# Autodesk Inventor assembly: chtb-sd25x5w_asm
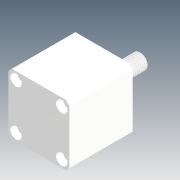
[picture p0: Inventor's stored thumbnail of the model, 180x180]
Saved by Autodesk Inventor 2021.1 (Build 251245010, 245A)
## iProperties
Company: Microsoft
Created: 2018-05
Part Number: chtb-sd25x5w_asm
Description: STEP AP214
Document SubType Name: Assembly
Designer: user
Title: chtb-sd25x5w_asm.STEP
Author: Windows
Revision Number: ÈÎºÎ
Sending System: SolidWorks 2015
Preprocessor: SwSTEP 2.0
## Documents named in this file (4)
- D:\Vault_2016\Projekty\Clamptek\Hydraulic\CHTB\CHTB-25\Inventor\chtb-sd25x5w\chtb-sd25x5w_asm.iam
- D:\Vault_2016\Projekty\Clamptek\Hydraulic\CHTB\CHTB-25\Inventor\chtb-sd25x5w\CHTB-25QG.ipt
- D:\Vault_2016\Projekty\Clamptek\Hydraulic\CHTB\CHTB-25\Inventor\chtb-sd25x5w\CHTB-SD25X5NBT.ipt
- D:\Vault_2016\Projekty\Clamptek\Hydraulic\CHTB\CHTB-25\Inventor\chtb-sd25x5w\CHTB-SD25X5WHSG.ipt
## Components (3 placed, 3 different names)
1. CHTB-25QG_1
2. CHTB-SD25X5NBT_2
3. CHTB-SD25X5WHSG_3
